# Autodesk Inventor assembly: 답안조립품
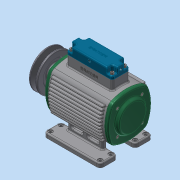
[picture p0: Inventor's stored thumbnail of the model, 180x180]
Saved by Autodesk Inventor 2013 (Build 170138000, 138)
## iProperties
Created: 2015-11
Part Number: 답안조립품
Document SubType Name: Assembly
Designer: dgall
Author: dgall
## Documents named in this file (18)
- C:\Users\dgall\Desktop\351109V1012\답안조립품.iam
- C:\Users\dgall\Desktop\351109V1012\1. 본체.ipt
- C:\Users\dgall\Desktop\351109V1012\4. 베어링 6203.ipt
- C:\Users\dgall\Desktop\351109V1012\2. 뒷커버.ipt
- C:\Users\dgall\Desktop\351109V1012\6. 볼트 M4 x 12.ipt
- C:\Users\dgall\Desktop\351109V1012\7. 축.ipt
- C:\Users\dgall\Desktop\351109V1012\12. 키 - 5 x 5 x 18.ipt
- C:\Users\dgall\Desktop\351109V1012\3. 앞커버.ipt
- C:\Users\dgall\Desktop\351109V1012\5. 오일실 17 30 8.ipt
- C:\Users\dgall\Desktop\351109V1012\11. V-벨트풀리.ipt
- C:\Users\dgall\Desktop\351109V1012\13. 멈춤나사 M4x5.ipt
- C:\Users\dgall\Desktop\351109V1012\14. 슬라이드.ipt
- C:\Users\dgall\Desktop\351109V1012\15. 스프링1.ipt
- C:\Users\dgall\Desktop\351109V1012\16. 스프링2.ipt
- C:\Users\dgall\Desktop\351109V1012\17. 스프링3.ipt
- C:\Users\dgall\Desktop\351109V1012\8. 부시.ipt
- C:\Users\dgall\Desktop\351109V1012\9. 헤더커버.ipt
- C:\Users\dgall\Desktop\351109V1012\10. 볼트 M4 x 16.ipt
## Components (32 placed, 17 different names)
1. 1. 본체:1
2. 7-베어링 6203:1
3. 2. 뒷커버:1
4. 6. 볼트 M4 x 12:1
5. 6. 볼트 M4 x 12:2
6. 6. 볼트 M4 x 12:3
7. 6. 볼트 M4 x 12:4
8. 7. 축:1
9. 12. 키 - 5 x 5 x 18:1
10. 3. 앞커버:1
11. 7-베어링 6203:2
12. 5. 오일실 17 30 8:1
13. 6. 볼트 M4 x 12:5
14. 6. 볼트 M4 x 12:6
15. 6. 볼트 M4 x 12:7
16. 6. 볼트 M4 x 12:8
17. 11. V-벨트풀리:1
18. 13. 멈춤나사 M4x5:1
19. 14. 슬라이드:1
20. 14. 슬라이드:2
21. 14. 슬라이드:3
22. 15. 스프링1:1
23. 16. 스프링2:1
24. 17. 스프링3:1
25. 8. 부시:1
26. 8. 부시:2
27. 8. 부시:3
28. 9. 헤더커버:1
29. 10. 볼트 M4 x 16:1
30. 10. 볼트 M4 x 16:2
31. 10. 볼트 M4 x 16:3
32. 10. 볼트 M4 x 16:4
